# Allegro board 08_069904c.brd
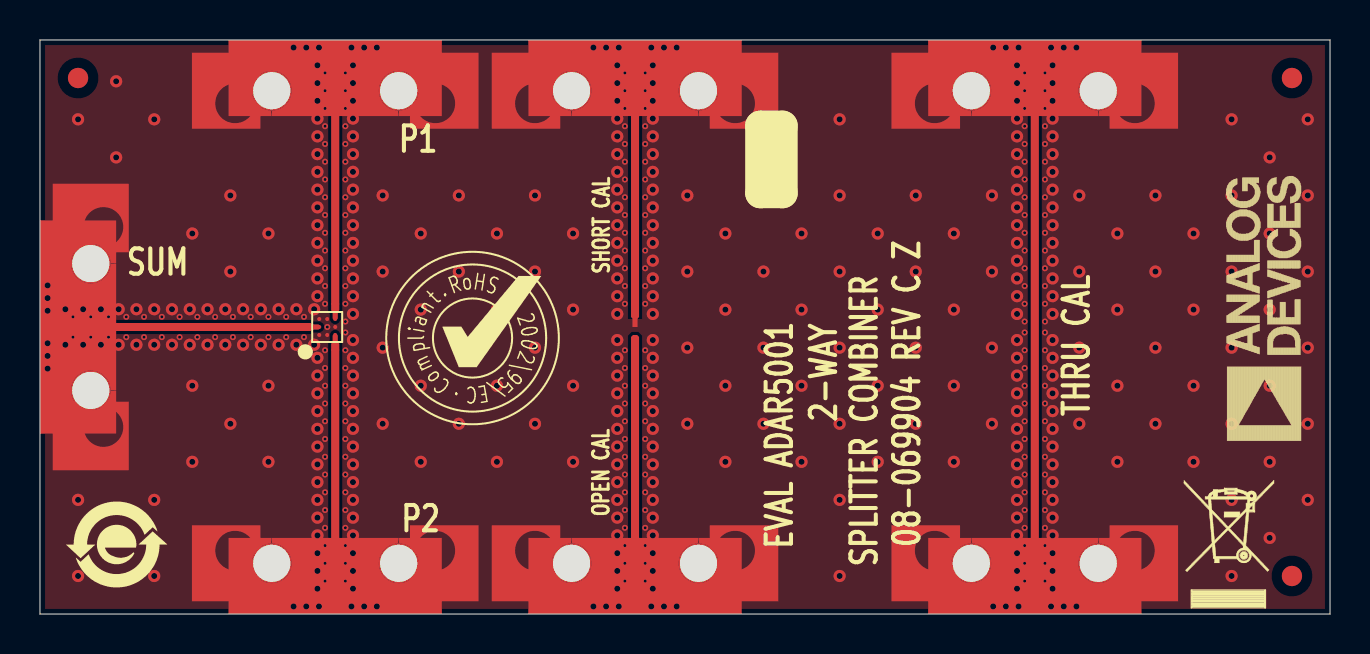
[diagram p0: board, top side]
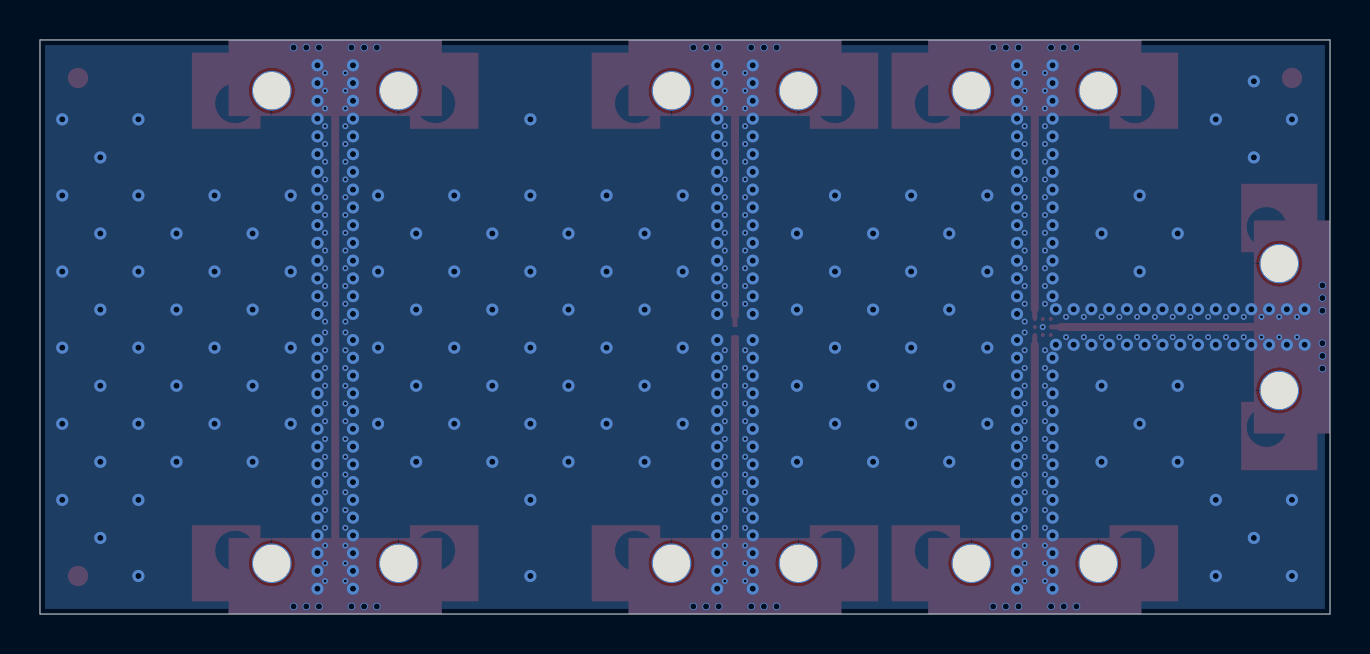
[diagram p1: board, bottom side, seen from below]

Outline 64.54 x 28.74 mm; copper layers: TOP, L2_GND, L3_GND, BOTTOM. Coordinates in mm from the lower left corner of the outline.
Outline path: 0,28.74 0,0 64.54,0 64.54,28.74 0,28.74

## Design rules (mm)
constraint set DEFAULT: min track width 0.203
net group RF_E: nets THRU_CAL

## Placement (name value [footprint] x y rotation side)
J1  ELF40-001  [CNSMAELF40-001]  14.77 28.74 90 top
J2  ELF40-001  [CNSMAELF40-001]  14.77 0 270 top
J3  ELF40-001  [CNSMAELF40-001]  0 14.37 180 top
J4  ELF40-001  [CNSMAELF40-001]  29.77 28.74 90 top
J5  ELF40-001  [CNSMAELF40-001]  29.77 0 270 top
J6  ELF40-001  [CNSMAELF40-001]  49.77 28.74 90 top
J7  ELF40-001  [CNSMAELF40-001]  49.77 0 270 top
NOREF  -  []  -72.29 -117.71 0 top
NOREF#2  -  [unnamed#2]  1.91 26.84 0 top
NOREF#3  -  []  11.6 2.54 0 top
NOREF#4  -  []  152.34 35.58 0 top
NOREF#5  -  []  64.54 0 90 top
NOREF#6  -  []  0 0 0 top
NOREF#7  -  []  0 28.74 270 top
NOREF#8  -  [unnamed#2]  62.64 1.91 0 top
NOREF#9  -  []  61.53 242.59 0 top
NOREF#10  -  []  0 28.74 0 top
NOREF#11  -  []  3.84 3.48 0 top
NOREF#12  -  []  42.15 14.96 0 top
NOREF#13  -  []  -33.72 193.06 0 top
NOREF#14  -  []  57.39 -13.78 0 top
NOREF#15  -  []  11.6 2.54 0 top
NOREF#16  -  []  22.15 14.96 0 top
NOREF#17  -  []  0 0 0 top
NOREF#18  -  []  32.03 45.87 0 top
NOREF#19  -  []  22.39 -13.78 0 top
NOREF#20  -  []  64.54 0 90 top
NOREF#21  -  []  37.39 -13.78 0 top
NOREF#22  -  [unnamed#2]  62.64 26.84 0 top
NOREF#23  -  []  -9.72 206.5 0 top
NOREF#24  -  []  0 -7.03 0 top
NOREF#25  -  []  64.54 0 0 top
NOREF#26  -  []  21.64 13.82 0 top
NOREF#27  -  []  0 0 0 top
NOREF#28  -  []  64.54 28.74 180 top
NOREF#29  -  []  0 29.61 0 top
NOREF#30  -  []  7.15 14.96 0 top
NOREF#31  -  []  -72.29 -117.71 0 top
U1  ADAR5001  [WLCSP8_1_5X1_5]  14.37 14.37 0 top

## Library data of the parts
J1-J7 = CNBNC4P: User Part Number: UPN; Tolerance: N/A; alternate symbols: (CNSMAELF40-001_40GHZ); part number: CNBNC4P_SM-ELF40-001,E031590,CNSMAELF40-001; tolerance: N/A
U1 = ADAR5001: Tolerance: N/A; User Part Number: UPN; alternate symbols: (); part number: ADAR5001_SM-ADAR5001,E048900,WLCSP8_1_5X1_5; tolerance: N/A

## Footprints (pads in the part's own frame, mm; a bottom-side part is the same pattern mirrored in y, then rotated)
CNSMAELF40-001
  round 1.981 hole 1.854 unplated: (-2.54,3.175) (-2.54,-3.175)
  custom 0.103x0.103 smd: 1(-0.851,0)
  custom 0.953x0.953 smd: 2(-2.54,4.718) 3(-2.54,-4.718) 4(-1.905,0)
unnamed#2
  round 1.016 smd: (0,0)
WLCSP8_1_5X1_5
  round 0.203 smd: A1(-0.4,-0.4) A2(-0.4,0) A3(-0.4,0.4) B1(0,-0.4) B3(0,0.4) C1(0.4,-0.4) C2(0.4,0) C3(0.4,0.4)

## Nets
AGND: J1.2 J1.3 J1.4(SH3) J2.2 J2.3 J2.4(SH3) J3.2 J3.3 J3.4(SH3) J4.1 J4.2 J4.3 J4.4(SH3) J5.2 J5.3 J5.4(SH3) J6.2 J6.3 J6.4(SH3) J7.2 J7.3 J7.4(SH3) U1.A1 U1.A3 U1.B1 U1.B3 U1.C2
OPEN_CAL: J5.1
P1: J1.1 U1.C3
P2: J2.1 U1.C1
SUM: J3.1 U1.A2(SUM)
THRU_CAL: J6.1 J7.1

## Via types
v1: diameter 0.61, hole 0.305, TOP to BOTTOM, 324 vias
v2: diameter 0.3, hole 0.152, TOP to BOTTOM, 203 vias
v3: diameter 0.381, hole 0.305, TOP to BOTTOM, 42 vias

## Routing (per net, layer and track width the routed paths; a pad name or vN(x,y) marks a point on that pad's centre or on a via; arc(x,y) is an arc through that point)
AGND: length 12.3
  TOP w0.401: 29.77,15.54 J4.1
  vias: v1(1.27,15.26) v1(1.27,13.48) v1(1.91,24.77) v1(1.91,5.72) v1(1.91,1.91) v1(2.16,15.26) v1(2.16,13.48) v1(3.05,15.26) v1(3.05,13.48) v1(3.81,26.67) v1(3.81,22.86) v1(3.81,3.81) v1(3.94,15.26) v1(3.94,13.48) v1(4.83,15.26) v1(4.83,13.48) v1(5.72,24.77) v1(5.72,15.26) v1(5.72,13.48) v1(5.72,5.72) v1(5.72,1.91) v1(6.6,15.26) v1(6.6,13.48) v1(7.49,15.26) v1(7.49,13.48) v1(7.62,19.05) v1(7.62,11.43) v1(7.62,7.62) v1(8.38,15.26) v1(8.38,13.48) v1(9.27,15.26) v1(9.27,13.48) v1(9.53,20.96) v1(9.53,17.15) v1(9.53,9.53) v1(10.16,15.26) v1(10.16,13.48) v1(11.05,15.26) v1(11.05,13.48) v1(11.43,19.05) v1(11.43,11.43) v1(11.43,7.62) v1(11.94,15.26) v1(11.94,13.48) v1(12.83,15.26) v1(12.83,13.48) v1(13.72,15.26) v1(13.72,13.48) v1(13.88,27.47) v1(13.88,26.58) v1(13.88,25.69) v1(13.88,24.8) v1(13.88,23.91) v1(13.88,23.03) v1(13.88,22.14) v1(13.88,21.25) v1(13.88,20.36) v1(13.88,19.47) v1(13.88,18.58) v1(13.88,17.69) v1(13.88,16.8) v1(13.88,15.91) v1(13.88,12.83) v1(13.88,11.94) v1(13.88,11.05) v1(13.88,10.16) v1(13.88,9.27) v1(13.88,8.38) v1(13.88,7.49) v1(13.88,6.6) v1(13.88,5.71) v1(13.88,4.83) v1(13.88,3.94) v1(13.88,3.05) v1(13.88,2.16) v1(13.88,1.27) v1(15.66,27.47) v1(15.66,26.58) v1(15.66,25.69) v1(15.66,24.8) v1(15.66,23.91) v1(15.66,23.03) v1(15.66,22.14) v1(15.66,21.25) v1(15.66,20.36) v1(15.66,19.47) v1(15.66,18.58) v1(15.66,17.69) v1(15.66,16.8) v1(15.66,15.91) v1(15.66,15.02) v1(15.66,13.72) v1(15.66,12.83) v1(15.66,11.94) v1(15.66,11.05) v1(15.66,10.16) v1(15.66,9.27) v1(15.66,8.38) v1(15.66,7.49) v1(15.66,6.6) v1(15.66,5.71) v1(15.66,4.83) v1(15.66,3.94) v1(15.66,3.05) v1(15.66,2.16) v1(15.66,1.27) v1(17.15,20.96) v1(17.15,17.15) v1(17.15,13.34) v1(17.15,9.53) v1(19.05,19.05) v1(19.05,15.24) v1(19.05,11.43) v1(19.05,7.62) v1(20.96,20.96) v1(20.96,17.15) v1(20.96,13.34) v1(20.96,9.53) v1(22.86,19.05) v1(22.86,15.24) v1(22.86,11.43) v1(22.86,7.62) v1(24.77,20.96) v1(24.77,17.15) v1(24.77,13.34) v1(24.77,9.53) v1(26.67,19.05) v1(26.67,15.24) v1(26.67,11.43) v1(26.67,7.62) v1(28.88,27.47) v1(28.88,26.58) v1(28.88,25.69) v1(28.88,24.8) v1(28.88,23.91) v1(28.88,23.03) v1(28.88,22.14) v1(28.88,21.25) v1(28.88,20.36) v1(28.88,19.47) v1(28.88,18.58) v1(28.88,17.69) v1(28.88,16.8) v1(28.88,15.91) v1(28.88,15.02) v1(28.88,13.72) v1(28.88,12.83) v1(28.88,11.94) v1(28.88,11.05) v1(28.88,10.16) v1(28.88,9.27) v1(28.88,8.38) v1(28.88,7.49) v1(28.88,6.6) v1(28.88,5.71) v1(28.88,4.83) v1(28.88,3.94) v1(28.88,3.05) v1(28.88,2.16) v1(28.88,1.27) v1(30.66,27.47) v1(30.66,26.58) v1(30.66,25.69) v1(30.66,24.8) v1(30.66,23.91) v1(30.66,23.03) v1(30.66,22.14) v1(30.66,21.25) v1(30.66,20.36) v1(30.66,19.47) v1(30.66,18.58) v1(30.66,17.69) v1(30.66,16.8) v1(30.66,15.91) v1(30.66,15.02) v1(30.66,13.72) v1(30.66,12.83) v1(30.66,11.94) v1(30.66,11.05) v1(30.66,10.16) v1(30.66,9.27) v1(30.66,8.38) v1(30.66,7.49) v1(30.66,6.6) v1(30.66,5.71) v1(30.66,4.83) v1(30.66,3.94) v1(30.66,3.05) v1(30.66,2.16) v1(30.66,1.27) v1(32.39,20.96) v1(32.39,17.15) v1(32.39,13.34) v1(32.39,9.53) v1(34.29,19.05) v1(34.29,15.24) v1(34.29,11.43) v1(34.29,7.62) v1(36.2,20.96) v1(36.2,17.15) v1(36.2,13.34) v1(36.2,9.53) v1(38.1,19.05) v1(38.1,15.24) v1(38.1,11.43) v1(38.1,7.62) v1(40.01,24.77) v1(40.01,20.96) v1(40.01,17.15) v1(40.01,13.34) v1(40.01,9.53) v1(40.01,5.72) v1(40.01,1.91) v1(41.91,19.05) v1(41.91,15.24) v1(41.91,11.43) v1(41.91,7.62) v1(43.82,20.96) v1(43.82,17.15) v1(43.82,13.34) v1(43.82,9.53) v1(45.72,19.05) v1(45.72,15.24) v1(45.72,11.43) v1(45.72,7.62) v1(47.63,20.96) v1(47.63,17.15) v1(47.63,13.34) v1(47.63,9.53) v1(48.88,27.47) v1(48.88,26.58) v1(48.88,25.69) v1(48.88,24.8) v1(48.88,23.91) v1(48.88,23.03) v1(48.88,22.14) v1(48.88,21.25) v1(48.88,20.36) v1(48.88,19.47) v1(48.88,18.58) v1(48.88,17.69) v1(48.88,16.8) v1(48.88,15.91) v1(48.88,15.02) v1(48.88,13.72) v1(48.88,12.83) v1(48.88,11.94) v1(48.88,11.05) v1(48.88,10.16) v1(48.88,9.27) v1(48.88,8.38) v1(48.88,7.49) v1(48.88,6.6) v1(48.88,5.71) v1(48.88,4.83) v1(48.88,3.94) v1(48.88,3.05) v1(48.88,2.16) v1(48.88,1.27) v1(50.66,27.47) v1(50.66,26.58) v1(50.66,25.69) v1(50.66,24.8) v1(50.66,23.91) v1(50.66,23.03) v1(50.66,22.14) v1(50.66,21.25) v1(50.66,20.36) v1(50.66,19.47) v1(50.66,18.58) v1(50.66,17.69) v1(50.66,16.8) v1(50.66,15.91) v1(50.66,15.02) v1(50.66,13.72) v1(50.66,12.83) v1(50.66,11.94) v1(50.66,11.05) v1(50.66,10.16) v1(50.66,9.27) v1(50.66,8.38) v1(50.66,7.49) v1(50.66,6.6) v1(50.66,5.71) v1(50.66,4.83) v1(50.66,3.94) v1(50.66,3.05) v1(50.66,2.16) v1(50.66,1.27) v1(52,20.96) v1(52,17.15) v1(52,13.34) v1(52,9.53) v1(53.9,19.05) v1(53.9,15.24) v1(53.9,11.43) v1(53.9,7.62) v1(55.81,20.96) v1(55.81,17.15) v1(55.81,13.34) v1(55.81,9.53) v1(57.71,19.05) v1(57.71,15.24) v1(57.71,11.43) v1(57.71,7.62) v1(59.62,24.77) v1(59.62,20.96) v1(59.62,17.15) v1(59.62,13.34) v1(59.62,9.53) v1(59.62,5.72) v1(59.62,1.91) v1(61.52,22.86) v1(61.52,19.05) v1(61.52,15.24) v1(61.52,11.43) v1(61.52,7.62) v1(61.52,3.81) v1(63.43,24.77) v1(63.43,20.96) v1(63.43,17.15) v1(63.43,13.34) v1(63.43,9.53) v1(63.43,5.72) v2(1.65,14.88) v2(1.65,13.86) v2(2.54,14.88) v2(2.54,13.86) v2(3.43,14.88) v2(3.43,13.86) v2(4.32,14.88) v2(4.32,13.86) v2(5.21,14.88) v2(5.21,13.86) v2(6.1,14.88) v2(6.1,13.86) v2(6.99,14.88) v2(6.99,13.86) v2(7.87,14.88) v2(7.87,13.86) v2(8.76,14.88) v2(8.76,13.86) v2(9.65,14.88) v2(9.65,13.86) v2(10.54,14.88) v2(10.54,13.86) v2(11.43,14.88) v2(11.43,13.86) v2(12.32,14.88) v2(12.32,13.86) v2(13.21,14.88) v2(13.21,13.86) v2(14.26,27.09) v2(14.26,26.2) v2(14.26,25.31) v2(14.26,24.42) v2(14.26,23.53) v2(14.26,22.64) v2(14.26,21.76) v2(14.26,20.87) v2(14.26,19.98) v2(14.26,19.09) v2(14.26,18.2) v2(14.26,17.31) v2(14.26,16.42) v2(14.26,15.53) v2(14.26,13.21) v2(14.26,12.32) v2(14.26,11.43) v2(14.26,10.54) v2(14.26,9.65) v2(14.26,8.76) v2(14.26,7.87) v2(14.26,6.99) v2(14.26,6.1) v2(14.26,5.21) v2(14.26,4.32) v2(14.26,3.43) v2(14.26,2.54) v2(14.26,1.65) v2(14.38,14.37) v2(15.28,27.09) v2(15.28,26.2) v2(15.28,25.31) v2(15.28,24.42) v2(15.28,23.53) v2(15.28,22.64) v2(15.28,21.76) v2(15.28,20.87) v2(15.28,19.98) v2(15.28,19.09) v2(15.28,18.2) v2(15.28,17.31) v2(15.28,16.42) v2(15.28,15.53) v2(15.28,14.64) v2(15.28,14.1) v2(15.28,13.21) v2(15.28,12.32) v2(15.28,11.43) v2(15.28,10.54) v2(15.28,9.65) v2(15.28,8.76) v2(15.28,7.87) v2(15.28,6.99) v2(15.28,6.1) v2(15.28,5.21) v2(15.28,4.32) v2(15.28,3.43) v2(15.28,2.54) v2(15.28,1.65) v2(29.26,27.09) v2(29.26,26.2) v2(29.26,25.31) v2(29.26,24.42) v2(29.26,23.53) v2(29.26,22.64) v2(29.26,21.76) v2(29.26,20.87) v2(29.26,19.98) v2(29.26,19.09) v2(29.26,18.2) v2(29.26,17.31) v2(29.26,16.42) v2(29.26,15.53) v2(29.26,13.21) v2(29.26,12.32) v2(29.26,11.43) v2(29.26,10.54) v2(29.26,9.65) v2(29.26,8.76) v2(29.26,7.87) v2(29.26,6.99) v2(29.26,6.1) v2(29.26,5.21) v2(29.26,4.32) v2(29.26,3.43) v2(29.26,2.54) v2(29.26,1.65) v2(30.28,27.09) v2(30.28,26.2) v2(30.28,25.31) v2(30.28,24.42) v2(30.28,23.53) v2(30.28,22.64) v2(30.28,21.76) v2(30.28,20.87) v2(30.28,19.98) v2(30.28,19.09) v2(30.28,18.2) v2(30.28,17.31) v2(30.28,16.42) v2(30.28,15.53) v2(30.28,13.21) v2(30.28,12.32) v2(30.28,11.43) v2(30.28,10.54) v2(30.28,9.65) v2(30.28,8.76) v2(30.28,7.87) v2(30.28,6.99) v2(30.28,6.1) v2(30.28,5.21) v2(30.28,4.32) v2(30.28,3.43) v2(30.28,2.54) v2(30.28,1.65) v2(49.26,27.09) v2(49.26,26.2) v2(49.26,25.31) v2(49.26,24.42) v2(49.26,23.53) v2(49.26,22.64) v2(49.26,21.76) v2(49.26,20.87) v2(49.26,19.98) v2(49.26,19.09) v2(49.26,18.2) v2(49.26,17.31) v2(49.26,16.42) v2(49.26,15.53) v2(49.26,14.64) v2(49.26,14.1) v2(49.26,13.21) v2(49.26,12.32) v2(49.26,11.43) v2(49.26,10.54) v2(49.26,9.65) v2(49.26,8.76) v2(49.26,7.87) v2(49.26,6.99) v2(49.26,6.1) v2(49.26,5.21) v2(49.26,4.32) v2(49.26,3.43) v2(49.26,2.54) v2(49.26,1.65) v2(50.28,27.09) v2(50.28,26.2) v2(50.28,25.31) v2(50.28,24.42) v2(50.28,23.53) v2(50.28,22.64) v2(50.28,21.76) v2(50.28,20.87) v2(50.28,19.98) v2(50.28,19.09) v2(50.28,18.2) v2(50.28,17.31) v2(50.28,16.42) v2(50.28,15.53) v2(50.28,14.64) v2(50.28,14.1) v2(50.28,13.21) v2(50.28,12.32) v2(50.28,11.43) v2(50.28,10.54) v2(50.28,9.65) v2(50.28,8.76) v2(50.28,7.87) v2(50.28,6.99) v2(50.28,6.1) v2(50.28,5.21) v2(50.28,4.32) v2(50.28,3.43) v2(50.28,2.54) v2(50.28,1.65) v3(0.38,16.45) v3(0.38,15.82) v3(0.38,15.18) v3(0.38,13.56) v3(0.38,12.92) v3(0.38,12.29) v3(12.69,28.36) v3(12.69,0.38) v3(13.32,28.36) v3(13.32,0.38) v3(13.96,28.36) v3(13.96,0.38) v3(15.58,28.36) v3(15.58,0.38) v3(16.22,28.36) v3(16.22,0.38) v3(16.85,28.36) v3(16.85,0.38) v3(27.69,28.36) v3(27.69,0.38) v3(28.32,28.36) v3(28.32,0.38) v3(28.96,28.36) v3(28.96,0.38) v3(30.58,28.36) v3(30.58,0.38) v3(31.22,28.36) v3(31.22,0.38) v3(31.85,28.36) v3(31.85,0.38) v3(47.69,28.36) v3(47.69,0.38) v3(48.32,28.36) v3(48.32,0.38) v3(48.96,28.36) v3(48.96,0.38) v3(50.58,28.36) v3(50.58,0.38) v3(51.22,28.36) v3(51.22,0.38) v3(51.85,28.36) v3(51.85,0.38)
OPEN_CAL: length 12.3
  TOP w0.401: 29.77,13.2 J5.1
P1: length 12.3
  TOP w0.401: 14.77,15.54 J1.1
P2: length 12.3
  TOP w0.401: 14.77,13.2 J2.1
SUM: length 12.3
  TOP w0.401: 13.2,14.37 J3.1
THRU_CAL: length 27
  TOP w0.401: J6.1 J7.1

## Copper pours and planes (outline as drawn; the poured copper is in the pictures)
AGND on TOP: 0.25,9.04 0,9.04 0,19.7 0.25,19.7 0.25,28.49 9.44,28.49 9.44,28.74 20.1,28.74 20.1,28.49 24.44,28.49 24.44,28.74 35.1,28.74 35.1,28.49 44.44,28.49 44.44,28.74 55.1,28.74 55.1,28.49 64.29,28.49 64.29,0.25 55.1,0.25 55.1,0 44.44,0 44.44,0.25 35.1,0.25 35.1,0 24.44,0 24.44,0.25 20.1,0.25 20.1,0 9.44,0 9.44,0.25 0.25,0.25 ; 1 cut-out
AGND on BOTTOM, L2_GND, L3_GND: 0.25,9.04 0,9.04 0,19.7 0.25,19.7 0.25,28.49 9.44,28.49 9.44,28.74 20.1,28.74 20.1,28.49 24.44,28.49 24.44,28.74 35.1,28.74 35.1,28.49 44.44,28.49 44.44,28.74 55.1,28.74 55.1,28.49 64.29,28.49 64.29,0.25 55.1,0.25 55.1,0 44.44,0 44.44,0.25 35.1,0.25 35.1,0 24.44,0 24.44,0.25 20.1,0.25 20.1,0 9.44,0 9.44,0.25 0.25,0.25

Small or netless copper shapes (teardrops, artwork), in the pictures only: 6 on TOP

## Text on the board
Ref Des/Silkscreen Bottom: SILKSCREEN-02
User.Comments: (SEE NOTE#7) | MATE ENTRY | 4.    RoHS COMPLIANCE: ASSEMBLY VENDOR SHOULD ASSURE COMPLIANCE | 5.    BOARDS TO BE SHIPPED SINGULATED AFTER ASSEMBLY PROCESS | 7.    DO NOT SOLDER CENTER PIN OF MFG_PN: ELF40-001 | INSTALL J1, J2, & J3 AS DECLARED FROM BOM | WITH LEAD-FREE AND RoHS PCB ASSEMBLY STANDARDS (EU RoHS | SMOOTHEN EDGES AND FREE FROM BURS AFTER DEPANELIZATION PROCESS | DIRECTIVE 2002/95/EC).
Ref Des/Silkscreen Top: OPEN CAL | SHORT CAL | SUM | P1 | P2 | EVAL ADAR5001 | 2-WAY | SPLITTER COMBINER | 08-069904 REV C Z | THRU CAL
XSECTION_CHART: *  SURFACE - AIR | * SOLDERMASK_TOP MASK - POLYIMIDE | L1 TOP CONDUCTOR - COPPER | *  DIELECTRIC - ROGERS_RO4350B | L2 L2_GND PLANE - COPPER | *  DIELECTRIC - PREPREG | L3 L3_GND PLANE - COPPER | *  DIELECTRIC - 370HR | L4 BOTTOM CONDUCTOR - COPPER | * SOLDERMASK_BOTTOM MASK - POLYIMIDE | DESIGN CROSS SECTION CHART | ___________________________ | TOTAL THICKNESS 62 MIL | 1-4
PAGE_OUTLINE: ANALOG DEVICES | 600-01992-00-2 | B/2 | B1 | C | CHANGED PER QC210819 | AS PER ECR-107298 | AS PER ECR-114584 | 27SEP21 | 29MAR22 | 30MAY23 | G. FOLEY | N.BLASE2 | E.CHOJNACKI
DIMENSION: METAL-01 | .062/.067 | METAL-01  1/2oz Cu | METAL-02  1/2oz Cu | METAL-03  1/2oz Cu | METAL-04  1/2oz Cu | SILKSCREEN-01 | SOLDERMASK-01 | RO4350B CORE .010 _.001 (CRITICAL) | PREPREG A/R | 370HR CORE A/R | SOLDERMASK-02 | 16. | 17. | 1. | 2. | 3. | 4. | 5. | 6. | 7. | 8. | 9. | 10. | 11. | 12. | 13. | 14. | 15. | VENDOR MAY ADD E-TEST STAMP TO PCB. VENDOR SHALL NOT ADD NAME, LOGO, | DATE CODE, UL LISTING OR ANY OTHER MARKING TO ANY VISIBLE LAYER. | BOARDS MUST PASS VISUAL INSPECTION PER IPC-A-600 CLASS 2. | MATERIAL: MULTILAYER. OVERALL STACK UP AS SHOWN. TYPE ROGERS 4350B, | HALF OUNCE COPPER BOTH SIDES. | 370HR TO BE USED AS FILLER TO MEET CRITICAL OVERALL THICKNESS. | FINISH: ENIG PER IPC-4552. | PLATED THRU HOLES: .001 MINIMUM WALL THICKNESS. | HOLE SIZES AND POSITIONS PER ARTWORK AND/OR DRILL FILE. | ALL HOLES TO BE LOCATED WITHIN _.003 OF THE CENTER OF THE PAD | OR OTHER TRUE POSITION. | FRONT TO BACK REGISTRATION _.003 MAX. | BOARD WARPAGE: <.010 PER LINEAR INCH. | SILKSCREEN: TOP SIDE ONLY WITH WHITE EPOXY INK. DLP OR LPI PROCESS PREFERRED. | SOLDERMASK: LPI SOLDERMASK BOTH SIDES. COLOR: GREEN REGISTRATION: _.004 MAX. | "SIZE" IN DRILL LEGEND IS IN MILS AND REFERS TO FINISHED HOLE SIZE. | MANUFACTURE PER IPC-6012 CLASS 2. | METAL-01 CRITICAL LINE WIDTH = .0158 _.001. ADJUST PROCESS TO ACHIEVE WIDTH. | ALL .006 AND .012 VIAS TO BE FILLED WITH NON-CONDUCTIVE VIA FILL AND | OVERPLATED WITH Cu BOTH SIDES. | PLATING THICKNESS .002 _.0005 FOR METAL-01 AND METAL-04. | ARTWORK IS 1:1. VENDOR TO ADJUST FOR ETCH FACTOR. | ANALOG DEVICES FEDERAL LLC | 20 Alpha Road | Chelmsford, MA 01824 | .XX | .XXX | .XXXX | ANGLES | DRAWING PRACTICES PER | ASME Y14.100 | INTERPRET DIMENSIONS & | TOLERANCES PER ASME | Y14.5-2009 | UNLESS OTHERWISE | SPECIFIED: | DIMENSIONS ARE IN INCHES | [mm] | TOLERANCES: | _.01 | _.005 | _.0020 | _.5 DEG. | DRAWN BY | ENGINEER | M, LYONS | B. SAM | THIRD ANGLE | PROJECTION | 2 | 1 | CHANGED PER QC210819 | ENGINEERING RELEASE PER QC200739 | SOURCE FILE: PADS | DO NOT SCALE DRAWING | DATE | 07/21/20 | TITLE | SCALE: | SIZE | CODE ID NO. | PROPRIETARY TO ANALOG DEVICES, INC. | DWG NO. | WT: | 09/27/2021 | 08/31/2020 | SHEET: | G. FOLEY | M. LYONS | REV | VENDOR NOTES: | SPECIAL REQUIREMENTS: | NOTES: | UNLESS OTHERWISE SPECIFIED: | ZONE | REVISION | DESCRIPTION | NONE | N/A | APPROVED | 1 OF 1 | PCB, EVAL, | 4-WAY SPLITTER-COMBINER | 600-01992-00 | STACK UP | A | 7EMW9
BODY_CENTER: DECIMALS | .XX +-.010 | .XXX +-.005 | .XXXX +-.0050 | TOLERANCES | FRACTIONS | +-1/32 | ANGLES | +- | 2 | TEMPLATE ENGINEER | HARDWARE SERVICES | HARDWARE SYSTEMS | TEST ENGINEER | COMPONENT ENGINEER | TEST PROCESS | HARDWARE RELEASE | DESIGNER | PTD ENGINEER | CHECKER | UNLESS OTHERWISE SPECIFIED | DIMENSIONS ARE IN INCHES | SILKSCREEN-01 | MATERIAL | FINISH | DO NOT SCALE DWG | M.VALE | A.GIRON | K.JABATAN | N.CORDOVA | M.LYONS | N.BLASE | APPROVAL | 24MAR22 | 21AUG20 | DATE | TITLE | SIZE | SCALE | FSCM NO | DRAWING NUMBER | SHEET | OF | REV | 804 WOBURN STREET | WILMINGTON, MA 01887 | 1/1 | A/1 | B/2 | B1 | REVISIONS | DESCRIPTION | INITIAL RELEASE / ENGINEERING RELEASE PER QC200739 | CHANGED PER QC210819 | AS PER ECR-107711 | 27SEP21 | 14MAR22 | WWM | DIVISION | 1 | APPROVED | M. LYONS | G. FOLEY | N.BLASE2 | ASSEMBLY | 4-WAY SPLITTER-COMBINER | PRIMARY SIDE | C | 24355 | 01 | CUSTOMER EVALUATION Z | -069903 | B | D | A | 4 | 3
DISPLAY_TOP: SOLDERMASK-02
DISPLAY_BOTTOM: SOLDERMASK-01
User.14: L2 GND | 08-      -06
User.15: L3 GND | 08-      -07
User.18: ROHS COMPLIANCE NOTE:  HOMOGENOUS MATERIALS IN THIS BOARD SHALL BE COMPLIANT | THE EU RoHS DIRECTIVE 2002/95/EC | 16.    BOARDS TO BE SHIPPED IN ARRAY AND KEEP INTACT. | 17.    PANEL TO BE SUBJECTED TO CUSTOMER'S APPROVAL. | 18.    PANELED SOLDER PASTE STENCIL SHOULD BE SENT TO THE CUSTOMER. | 15.    THRU VIAS FILLED WITH NON-CONDUCTIVE EPOXY AND PLATED OVER. | COPLANAR ON BOTH SIDES WITHIN .001 INCH PRIOR TO FINAL PLATING.
User.19: METAL-02 | METAL-03 | METAL-04
User.21: LAYER 1 | 50 OHMS;CPWG | LAYER 2 | 0.0158" | 0.006" | LAYER | IMPEDANCE | REFERENCE | LINE WIDTH | SPACING | RO4350B CORE .010 +/- 10% (CRITICAL) | - | " " | IMPEDANCE TOLERANCE +/-10% | CPWG-COPLANAR WAVE GUIDE | (REF) | DIA MAX/SEE NOTE#15 | 2 | IMPEDANCE TABLE
User.45: FIGURE | SIZE | 6.0 | 12.0 | 73.0 | PLATED | NON-PLATED | DRILL CHART: TOP to BOTTOM | ALL UNITS ARE IN MILS | QTY | 203 | 366 | 14 | TOLERANCE/NOTES
